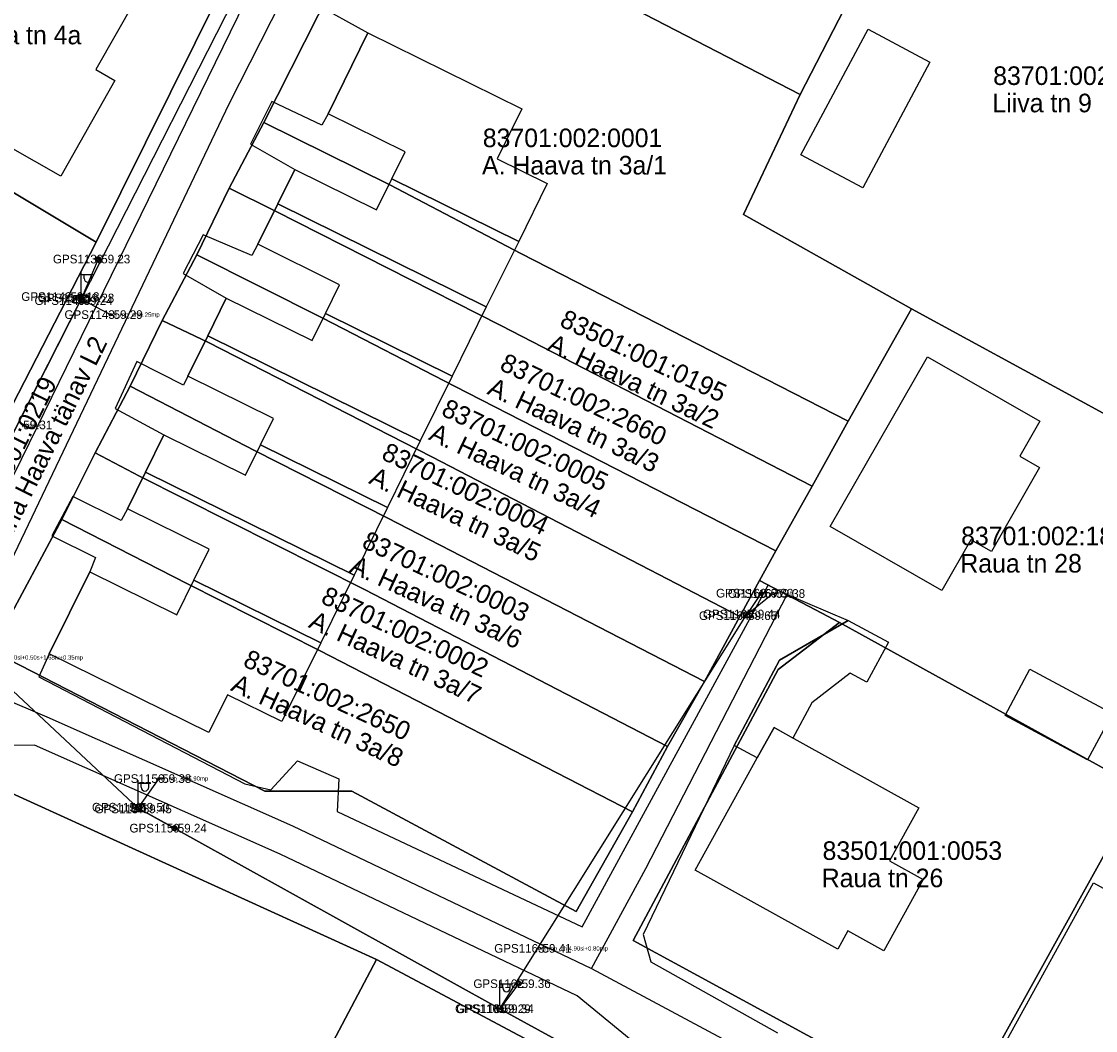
# Model space of a CAD drawing. Extents: x 580119 to 583377, y 6518915 to 6520820.
# Drawn here: x 581859.6 to 581946.3, y 6520066.7 to 6520148.1 of the extents above; entities that cross this region are included whole.
import ezdxf

# ---------------------------------------------------------------- set-up
doc = ezdxf.new("R2010")
doc.units = 0
for name, color, linetype in [('ELRAJATISMP', 7, 'Continuous'), ('Hoone Elu- või ühiskondlik hoone', 7, 'Continuous'), ('Hoone Kõrval- või tootmishoone', 7, 'Continuous'), ('L_AADRESS', 7, 'Continuous'), ('MAAMUDEL', 7, 'Continuous'), ('MOOTKORG-EH2000', 7, 'Continuous'), ('MOOTMPUNKT', 7, 'Continuous'), ('MOOTNR', 7, 'Continuous'), ('MPOHULIIN', 7, 'Continuous'), ('PIIR', 7, 'Continuous'), ('POST', 7, 'Continuous'), ('Rippe kõrgus', 7, 'Continuous'), ('SIOHULIIN', 7, 'Continuous'), ('SIRAJATIS', 7, 'Continuous'), ('Tee Liiklusala', 7, 'Continuous'), ('Tee Tänav Kruuskate', 7, 'Continuous'), ('Tee Tänav Püsikate', 7, 'Continuous'), ('TUNNUS', 7, 'Continuous')]:
    doc.layers.add(name, color=color, linetype=linetype)

msp = doc.modelspace()

# ---------------------------------------------------------------- linework, layer by layer
at = {"layer": 'ELRAJATISMP'}
for p, q in [((581864.289, 6520126), (581864.289, 6520125.404)), ((581864.56, 6520126), (581864.56, 6520125.404))]:
    msp.add_line(p, q, dxfattribs=at)
msp.add_lwpolyline([(581863.827, 6520126), (581865.022, 6520126), (581865.022, 6520125.404), (581863.827, 6520125.404)], close=True, dxfattribs=at)
at = {"layer": 'Hoone Elu- või ühiskondlik hoone'}
for points in [[(581852.13, 6520141.691), (581859.68, 6520154.991), (581868.781, 6520149.822), (581865.61, 6520144.241), (581867.15, 6520143.372), (581862.77, 6520135.652)], [(581902.047, 6520135.043), (581899.747, 6520130.38), (581889.508, 6520135.433), (581890.576, 6520137.597), (581884.36, 6520140.661), (581887.58, 6520147.2), (581900.005, 6520141.064), (581898.015, 6520137.033)], [(581881.66, 6520136.191), (581888.271, 6520132.926), (581889.508, 6520135.433), (581899.747, 6520130.38), (581897.134, 6520125.086), (581880.287, 6520133.402)], [(581897.134, 6520125.086), (581894.382, 6520119.509), (581884.144, 6520124.562), (581885.29, 6520126.882), (581878.68, 6520130.141), (581880.287, 6520133.402)], [(581876.13, 6520125.79), (581883.06, 6520122.371), (581884.144, 6520124.562), (581894.382, 6520119.509), (581891.803, 6520114.282), (581874.634, 6520122.755)], [(581891.803, 6520114.282), (581889.145, 6520108.894), (581878.907, 6520113.947), (581879.961, 6520116.082), (581873.03, 6520119.501), (581874.634, 6520122.755)], [(581941.81, 6520112.129), (581937.922, 6520105.356), (581936.269, 6520106.302), (581933.91, 6520102.203), (581924.894, 6520107.377), (581932.761, 6520121.066), (581941.821, 6520115.869), (581940.209, 6520113.052)], [(581871.09, 6520114.761), (581877.699, 6520111.498), (581878.907, 6520113.947), (581889.145, 6520108.894), (581886.457, 6520103.445), (581869.61, 6520111.76)], [(581886.457, 6520103.445), (581883.759, 6520097.977), (581873.522, 6520103.031), (581874.757, 6520105.534), (581868.15, 6520108.801), (581869.61, 6520111.76)], [(581865.111, 6520103.718), (581872.148, 6520100.246), (581873.522, 6520103.031), (581883.759, 6520097.977), (581880.623, 6520091.621), (581876.224, 6520093.793), (581874.715, 6520090.732), (581861.835, 6520097.078)], [(581921.974, 6520090.248), (581932.067, 6520084.655), (581929.697, 6520080.379), (581932.408, 6520078.876), (581929.222, 6520073.127), (581926.335, 6520074.727), (581925.519, 6520073.254), (581914.003, 6520079.636), (581919.019, 6520088.686), (581920.375, 6520091.134)], [(581962.074, 6520065.922), (581956.359, 6520055.543), (581948.327, 6520059.958), (581949.203, 6520061.558), (581943.988, 6520064.433), (581943.193, 6520062.985), (581938.865, 6520065.367), (581946.165, 6520078.618), (581950.761, 6520076.091), (581949.1, 6520073.068)]]:
    msp.add_lwpolyline(points, close=True, dxfattribs=at)
at = {"layer": 'Hoone Kõrval- või tootmishoone'}
for points in [[(581932.958, 6520144.83), (581927.546, 6520134.692), (581922.545, 6520137.362), (581927.958, 6520147.499)], [(581929.598, 6520098.039), (581927.871, 6520094.811), (581926.527, 6520095.53), (581923.411, 6520093.122), (581921.896, 6520090.291), (581920.375, 6520091.134), (581919.019, 6520088.686), (581917.139, 6520089.692), (581920.817, 6520096.567), (581926.353, 6520099.775)], [(581939.026, 6520092.103), (581941.036, 6520095.842), (581947.686, 6520092.263), (581945.676, 6520088.523)]]:
    msp.add_lwpolyline(points, close=True, dxfattribs=at)
at = {"layer": 'MOOTMPUNKT'}
for centre in [(581865.781, 6520128.951), (581863.293, 6520125.922), (581864.361, 6520125.596), (581864.488, 6520125.808), (581866.782, 6520124.467), (581919.323, 6520101.984), (581920.275, 6520101.957), (581918.016, 6520100.17), (581918.273, 6520100.3), (581870.708, 6520087.02), (581868.932, 6520084.708), (581869.133, 6520084.571), (581871.96, 6520083.02), (581901.412, 6520073.315), (581899.73, 6520070.465), (581898.112, 6520068.445), (581898.353, 6520068.441)]:
    msp.add_circle(centre, 0.1, dxfattribs=at)
at = {"layer": 'MPOHULIIN'}
for p, q in [((581864.425, 6520125.702), (581853.741, 6520104.726)), ((581864.425, 6520125.702), (581866.782, 6520124.467)), ((581869.033, 6520084.64), (581870.708, 6520087.02))]:
    msp.add_line(p, q, dxfattribs=at)
for points in [[(581899.05, 6520195.285), (581878.977, 6520154.314), (581864.425, 6520125.702), (581863.293, 6520125.922)], [(581898.232, 6520068.443), (581918.145, 6520100.235), (581920.275, 6520101.957)], [(581854.232, 6520098.424), (581869.033, 6520084.64), (581898.232, 6520068.443), (581929.764, 6520051.169), (581964.377, 6520031.774), (581989.598, 6520017.96), (582014.996, 6520004.053), (582041.548, 6519986.36), (582056.944, 6519974.839)]]:
    msp.add_lwpolyline(points, dxfattribs=at)
at = {"layer": 'PIIR'}
for points in [[(581818.25, 6520012.64), (581808.31, 6520018.92), (581824.83, 6520050.4), (581836.47, 6520072.82), (581851.4, 6520101.52), (581829.9, 6520114.5), (581832.4, 6520118.89), (581853.07, 6520105.93), (581865.62, 6520130.32), (581875.62, 6520150.43), (581897.71, 6520194.09), (581905.22, 6520189.53), (581889.06, 6520159.5), (581879.18, 6520139.97), (581876.38, 6520134.67), (581873.75, 6520129.28), (581870.97, 6520123.99), (581868.38, 6520118.69), (581865.54, 6520113.3), (581862.86, 6520107.92), (581858.03, 6520098.95), (581858.58, 6520096.63), (581855.23, 6520085.11)], [(581905.22, 6520189.53), (581937.09, 6520170.6), (581922.47, 6520142.22), (581889.06, 6520159.5)], [(581917.89, 6520132.56), (581922.47, 6520142.22), (581937.09, 6520170.6), (581968.64, 6520151.74), (581949.67, 6520115.03), (581931.46, 6520124.92)], [(581846.68, 6520162.43), (581848.92, 6520166.07), (581875.62, 6520150.43), (581865.62, 6520130.32), (581837.68, 6520147.06)], [(581889.06, 6520159.5), (581922.47, 6520142.22), (581917.89, 6520132.56), (581931.46, 6520124.92), (581926.36, 6520115.88), (581899.93, 6520129.4), (581889.34, 6520134.93), (581879.18, 6520139.97)], [(581823.73, 6520125.03), (581835.4, 6520143.6), (581837.68, 6520147.06), (581865.62, 6520130.32), (581853.07, 6520105.93), (581832.4, 6520118.89)], [(581876.38, 6520134.67), (581879.18, 6520139.97), (581889.34, 6520134.93), (581899.93, 6520129.4), (581926.36, 6520115.88), (581923.44, 6520110.63), (581898.3, 6520123.58), (581880.07, 6520132.83)], [(581873.75, 6520129.28), (581876.38, 6520134.67), (581880.07, 6520132.83), (581898.3, 6520123.58), (581923.44, 6520110.63), (581920.52, 6520105.4), (581894.56, 6520118.69), (581883.94, 6520124.19)], [(581873.75, 6520129.28), (581883.94, 6520124.19), (581894.56, 6520118.69), (581920.52, 6520105.4), (581919.2, 6520103.01), (581917.61, 6520100.1), (581892.74, 6520112.99), (581874.65, 6520122.24), (581870.97, 6520123.99)], [(581919.2, 6520103.01), (581920.52, 6520105.4), (581923.44, 6520110.63), (581926.36, 6520115.88), (581931.46, 6520124.92), (581949.67, 6520115.03), (581962.08, 6520107.97), (581949.99, 6520086.2), (581925.66, 6520099.62), (581923.71, 6520100.64)], [(581870.97, 6520123.99), (581874.65, 6520122.24), (581892.74, 6520112.99), (581917.61, 6520100.1), (581914.75, 6520094.85), (581889.14, 6520108.07), (581878.46, 6520113.46), (581868.38, 6520118.69)], [(581868.38, 6520118.69), (581878.46, 6520113.46), (581889.14, 6520108.07), (581914.75, 6520094.85), (581911.76, 6520089.61), (581887.29, 6520102.28), (581869.12, 6520111.43), (581865.54, 6520113.3)], [(581865.54, 6520113.3), (581869.12, 6520111.43), (581887.29, 6520102.28), (581911.76, 6520089.61), (581908.93, 6520084.35), (581883.66, 6520097.35), (581873.01, 6520102.73), (581862.86, 6520107.92)], [(581858.58, 6520096.63), (581858.03, 6520098.95), (581862.86, 6520107.92), (581873.01, 6520102.73), (581883.66, 6520097.35), (581908.93, 6520084.35), (581904.4, 6520076.28), (581886.27, 6520086), (581879.26, 6520086)], [(581935.27, 6520059.68), (581908.98, 6520073.94), (581920.7, 6520095.82), (581925.66, 6520099.62), (581949.99, 6520086.2)], [(581888.28, 6520072.43), (581876.44, 6520050.07), (581847.29, 6519995.61), (581818.25, 6520012.64), (581855.23, 6520085.11), (581858.5, 6520085.99)], [(581975.85, 6520071.52), (581961.38, 6520044.71), (581935.27, 6520059.68), (581949.99, 6520086.2)], [(581888.28, 6520072.43), (581930.04, 6520050.18), (581917.35, 6520027.64), (581908.22, 6520032.46), (581876.44, 6520050.07)]]:
    msp.add_lwpolyline(points, close=True, dxfattribs=at)
msp.add_lwpolyline([(581949.86, 6520009.55), (581943.51, 6520012.98), (581956.4, 6520035.78), (581930.04, 6520050.18), (581888.28, 6520072.43), (581858.5, 6520085.99), (581855.23, 6520085.11), (581858.58, 6520096.63), (581879.26, 6520086), (581886.27, 6520086), (581904.4, 6520076.28), (581908.93, 6520084.35), (581911.76, 6520089.61), (581914.75, 6520094.85), (581917.61, 6520100.1), (581919.2, 6520103.01), (581923.71, 6520100.64), (581925.66, 6520099.62), (581920.7, 6520095.82), (581908.98, 6520073.94), (581935.27, 6520059.68), (581961.38, 6520044.71)], dxfattribs=at)
at = {"layer": 'POST'}
for p, q in [((581864.425, 6520125.952), (581864.425, 6520127.952)), ((581864.425, 6520127.702), (581865.425, 6520127.702)), ((581864.651, 6520127.381), (581864.651, 6520127.702)), ((581865.264, 6520127.381), (581865.264, 6520127.702)), ((581864.425, 6520125.702), (581864.425, 6520125.702)), ((581869.033, 6520084.89), (581869.033, 6520086.89)), ((581869.033, 6520086.64), (581870.033, 6520086.64)), ((581869.259, 6520086.319), (581869.259, 6520086.64)), ((581869.872, 6520086.319), (581869.872, 6520086.64)), ((581869.033, 6520084.64), (581869.033, 6520084.64)), ((581898.232, 6520068.693), (581898.232, 6520070.693)), ((581898.232, 6520070.443), (581899.232, 6520070.443)), ((581898.459, 6520070.122), (581898.459, 6520070.443)), ((581899.072, 6520070.122), (581899.072, 6520070.443)), ((581898.232, 6520068.443), (581898.232, 6520068.443))]:
    msp.add_line(p, q, dxfattribs=at)
for points in [[(581865.781, 6520128.951), (581864.425, 6520125.702)], [(581919.323, 6520101.984), (581918.145, 6520100.235)], [(581871.96, 6520083.02), (581869.033, 6520084.64)], [(581899.73, 6520070.465), (581898.232, 6520068.443)]]:
    msp.add_lwpolyline(points, dxfattribs=at)
for centre, radius in [((581865.781, 6520128.951), 0.2), ((581864.425, 6520125.702), 0.25), ((581919.323, 6520101.984), 0.125), ((581919.323, 6520101.984), 0.105), ((581919.323, 6520101.984), 0.0851), ((581919.323, 6520101.984), 0.0651), ((581919.323, 6520101.984), 0.0451), ((581919.323, 6520101.984), 0.0251), ((581919.323, 6520101.984), 0.00511), ((581918.145, 6520100.235), 0.25), ((581869.033, 6520084.64), 0.25), ((581871.96, 6520083.02), 0.2), ((581899.73, 6520070.465), 0.2), ((581898.232, 6520068.443), 0.25)]:
    msp.add_circle(centre, radius, dxfattribs=at)
for centre in [(581864.958, 6520127.381), (581869.566, 6520086.319), (581898.765, 6520070.122)]:
    msp.add_arc(centre, 0.306, 180, 0, dxfattribs=at)
at = {"layer": 'SIOHULIIN'}
for points in [[(581853.741, 6520104.726), (581864.425, 6520125.702)], [(581869.033, 6520084.64), (581854.232, 6520098.424)], [(582041.183, 6519985.159), (582041.548, 6519986.36), (582014.996, 6520004.053), (581989.598, 6520017.96), (581964.377, 6520031.774), (581929.764, 6520051.169), (581898.232, 6520068.443), (581869.033, 6520084.64)]]:
    msp.add_lwpolyline(points, dxfattribs=at)
at = {"layer": 'SIRAJATIS'}
msp.add_lwpolyline([(581868.533, 6520084.94), (581869.533, 6520084.94), (581869.533, 6520084.34), (581868.533, 6520084.34)], close=True, dxfattribs=at)
for centre, radius in [((581868.833, 6520084.64), 0.0304), ((581868.833, 6520084.64), 0.029), ((581868.833, 6520084.64), 0.0277), ((581868.833, 6520084.64), 0.0263), ((581868.833, 6520084.64), 0.0249), ((581868.833, 6520084.64), 0.0236), ((581868.833, 6520084.64), 0.0222), ((581868.833, 6520084.64), 0.0209), ((581868.833, 6520084.64), 0.0195), ((581868.833, 6520084.64), 0.0181), ((581868.833, 6520084.64), 0.0168), ((581868.833, 6520084.64), 0.0154), ((581868.833, 6520084.64), 0.014), ((581868.833, 6520084.64), 0.0127), ((581868.833, 6520084.64), 0.0113), ((581868.833, 6520084.64), 0.00996), ((581868.833, 6520084.64), 0.0086), ((581868.833, 6520084.64), 0.00724), ((581868.833, 6520084.64), 0.00587), ((581868.833, 6520084.64), 0.00451), ((581868.833, 6520084.64), 0.00315), ((581868.833, 6520084.64), 0.00179), ((581868.833, 6520084.64), 0.000426), ((581869.233, 6520084.64), 0.0304), ((581869.233, 6520084.64), 0.029), ((581869.233, 6520084.64), 0.0277), ((581869.233, 6520084.64), 0.0263), ((581869.233, 6520084.64), 0.0249), ((581869.233, 6520084.64), 0.0236), ((581869.233, 6520084.64), 0.0222), ((581869.233, 6520084.64), 0.0209), ((581869.233, 6520084.64), 0.0195), ((581869.233, 6520084.64), 0.0181), ((581869.233, 6520084.64), 0.0168), ((581869.233, 6520084.64), 0.0154), ((581869.233, 6520084.64), 0.014), ((581869.233, 6520084.64), 0.0127), ((581869.233, 6520084.64), 0.0113), ((581869.233, 6520084.64), 0.00996), ((581869.233, 6520084.64), 0.0086), ((581869.233, 6520084.64), 0.00724), ((581869.233, 6520084.64), 0.00587), ((581869.233, 6520084.64), 0.00451), ((581869.233, 6520084.64), 0.00315), ((581869.233, 6520084.64), 0.00179), ((581869.233, 6520084.64), 0.000426)]:
    msp.add_circle(centre, radius, dxfattribs=at)
at = {"layer": 'Tee Liiklusala'}
for points in [[(581742.215, 6520054.723), (581805.663, 6520015.653), (581807.918, 6520015.737), (581809.742, 6520016.857), (581827.568, 6520051.921), (581835.83, 6520068.282), (581846.508, 6520088.672), (581848.263, 6520094.065), (581852.483, 6520100.961), (581835.959, 6520111.027), (581830.266, 6520114.149), (581828.794, 6520115.158), (581829.718, 6520117.195), (581830.788, 6520119.284), (581852.184, 6520107.138), (581853.36, 6520106.77), (581854.804, 6520106.704), (581855.859, 6520107.038), (581856.65, 6520107.81), (581859.04, 6520111.64), (581881.29, 6520157.17)], [(581883.176, 6520149.641), (581887.58, 6520147.2), (581884.36, 6520140.661), (581883.844, 6520139.761), (581879.822, 6520141.665), (581878.092, 6520138.218), (581881.66, 6520136.191), (581880.287, 6520133.402), (581878.68, 6520130.141), (581878.212, 6520129.24), (581874.28, 6520130.904), (581872.668, 6520127.776), (581876.13, 6520125.79), (581874.634, 6520122.755), (581873.03, 6520119.501), (581872.691, 6520118.772), (581868.912, 6520120.686), (581867.156, 6520116.888), (581871.09, 6520114.761), (581869.61, 6520111.76), (581868.15, 6520108.801), (581867.658, 6520107.855), (581863.74, 6520109.79), (581862.063, 6520106.623), (581865.585, 6520104.86), (581865.111, 6520103.718), (581861.835, 6520097.078), (581861.006, 6520095.224), (581877.624, 6520086.607), (581879.747, 6520086.119), (581881.89, 6520088.451), (581885.225, 6520087.003), (581885.08, 6520084.371), (581904.87, 6520075.047), (581919.887, 6520102.628), (581921.421, 6520101.874), (581926.353, 6520099.775), (581920.817, 6520096.567), (581917.139, 6520089.692), (581909.787, 6520074.427), (581910.406, 6520072.235), (581920.639, 6520066.499)], [(581951.622, 6520039.928), (581930.601, 6520052.21), (581908.83, 6520065.921), (581904.459, 6520069.499), (581880.476, 6520080.917), (581860.654, 6520089.709), (581856.965, 6520089.651), (581853.653, 6520088.441), (581850.79, 6520086.066), (581846.566, 6520077.855), (581840.27, 6520065.98), (581832.895, 6520051.299), (581814.422, 6520014.831), (581814.487, 6520011.909), (581816.356, 6520009.507), (581833.173, 6519999.999), (581968.761, 6519918.78)]]:
    msp.add_lwpolyline(points, dxfattribs=at)
at = {"layer": 'Tee Tänav Kruuskate'}
msp.add_lwpolyline([(581905.64, 6520071.702), (581910.01, 6520079.762), (581921.421, 6520101.874)], dxfattribs=at)
at = {"layer": 'Tee Tänav Püsikate'}
for points in [[(581904.384, 6520197.949), (581891.674, 6520171.939), (581884.02, 6520156.581), (581876.34, 6520141.461), (581857.05, 6520101.082)], [(581854.2, 6520095.172), (581861.65, 6520092.002), (581881.49, 6520083.202), (581905.64, 6520071.702)], [(581905.64, 6520071.702), (581919.26, 6520064.401), (581932.016, 6520054.279), (581952.685, 6520042.203), (581961.489, 6520039.036)]]:
    msp.add_lwpolyline(points, dxfattribs=at)

# ---------------------------------------------------------------- texts
at = {"layer": 'L_AADRESS'}
for s, p in [('A. Haava tn 4a', (581851.163, 6520146.282)), ('Liiva tn 9', (581938.002, 6520140.796)), ('A. Haava tn 3a/1', (581896.786, 6520135.777)), ('Raua tn 28', (581935.412, 6520103.647)), ('Raua tn 26', (581924.222, 6520078.251))]:
    msp.add_text(s, height=1.5, dxfattribs=at).set_placement(p)
for s, rotation, p in [('Anna Haava tänav L2', 63.70997, (581858.028, 6520104.927)), ('A. Haava tn 3a/2', 334.55105, (581901.961, 6520121.619)), ('A. Haava tn 3a/3', 334.55105, (581897.12, 6520118.092)), ('A. Haava tn 3a/4', 334.55105, (581892.405, 6520114.416)), ('A. Haava tn 3a/5', 334.55105, (581887.569, 6520110.881)), ('A. Haava tn 3a/6', 335.1256, (581886.003, 6520103.723)), ('A. Haava tn 3a/7', 335.1256, (581882.702, 6520099.26)), ('A. Haava tn 3a/8', 335.1256, (581876.416, 6520094.162))]:
    msp.add_text(s, height=1.5, rotation=rotation, dxfattribs=at).set_placement(p)
at = {"layer": 'MAAMUDEL'}
for s, p in [(' tv+side', (581859.481, 6520115.386)), (' mp_ohl', (581920.275, 6520101.782))]:
    msp.add_text(s, height=0.35, dxfattribs=at).set_placement(p)
at = {"layer": 'MOOTKORG-EH2000'}
for s, p in [(' 59.23', (581865.781, 6520128.601)), (' 59.18', (581863.293, 6520125.572)), (' 59.24', (581864.361, 6520125.246)), (' 59.28', (581864.488, 6520125.458)), (' 59.29', (581866.782, 6520124.117)), (' 59.31', (581859.481, 6520115.211)), (' 59.30', (581919.323, 6520101.634)), (' 59.38', (581920.275, 6520101.607)), (' 59.65', (581918.016, 6520099.82)), (' 59.44', (581918.273, 6520099.95)), (' 59.38', (581870.708, 6520086.67)), (' 59.50', (581868.932, 6520084.358)), (' 59.45', (581869.133, 6520084.221)), (' 59.24', (581871.96, 6520082.67)), (' 59.41', (581901.412, 6520072.965)), (' 59.36', (581899.73, 6520070.115)), (' 59.29', (581898.112, 6520068.095)), (' 59.34', (581898.353, 6520068.091))]:
    msp.add_text(s, height=0.7, dxfattribs=at).set_placement(p)
at = {"layer": 'MOOTNR'}
for s, p in [('GPS1139 ', (581862.141, 6520128.601)), ('GPS1142 ', (581859.583, 6520125.572)), ('GPS1140 ', (581860.652, 6520125.246)), ('GPS1141 ', (581860.918, 6520125.458)), ('GPS1143 ', (581863.073, 6520124.117)), ('GPS1166 ', (581915.684, 6520101.634)), ('GPS1167 ', (581916.635, 6520101.607)), ('GPS1164 ', (581914.306, 6520099.82)), ('GPS1165 ', (581914.633, 6520099.95)), ('GPS1156 ', (581867.069, 6520086.67)), ('GPS1158 ', (581865.292, 6520084.358)), ('GPS1157 ', (581865.494, 6520084.221)), ('GPS1159 ', (581868.32, 6520082.67)), ('GPS1163 ', (581897.772, 6520072.965)), ('GPS1162 ', (581896.09, 6520070.115)), ('GPS1161 ', (581894.612, 6520068.095)), ('GPS1160 ', (581894.713, 6520068.091))]:
    msp.add_text(s, height=0.7, dxfattribs=at).set_placement(p)
at = {"layer": 'Rippe kõrgus'}
for s, p in [(' el_mp_ohl6.25mp', (581866.782, 6520124.292)), (' el_mp_ohl5.30si+0.50s+1.65tv+0.35mp', (581855.953, 6520096.62)), (' el_mp_ohl5.90mp', (581870.708, 6520086.845)), (' el_mp_ohl4.90si+0.80mp', (581901.412, 6520073.14))]:
    msp.add_text(s, height=0.35, dxfattribs=at).set_placement(p)
at = {"layer": 'TUNNUS'}
for s, p in [('83701:002:0360', (581938.065, 6520143.001)), ('83701:002:0001', (581896.849, 6520137.982)), ('83701:002:1890', (581935.476, 6520105.852)), ('83501:001:0053', (581924.285, 6520080.457))]:
    msp.add_text(s, height=1.5, dxfattribs=at).set_placement(p)
for s, rotation, p in [('83501:001:0195', 334.55105, (581902.966, 6520123.583)), ('83701:002:2660', 334.55105, (581898.125, 6520120.055)), ('83401:001:0219', 63.70997, (581856.079, 6520105.96)), ('83701:002:0005', 334.55105, (581893.41, 6520116.38)), ('83701:002:0004', 334.55105, (581888.574, 6520112.845)), ('83701:002:0003', 335.1256, (581886.988, 6520105.697)), ('83701:002:0002', 335.1256, (581883.687, 6520101.234)), ('83701:002:2650', 335.1256, (581877.401, 6520096.135))]:
    msp.add_text(s, height=1.5, rotation=rotation, dxfattribs=at).set_placement(p)

doc.saveas('drawing.dxf')
